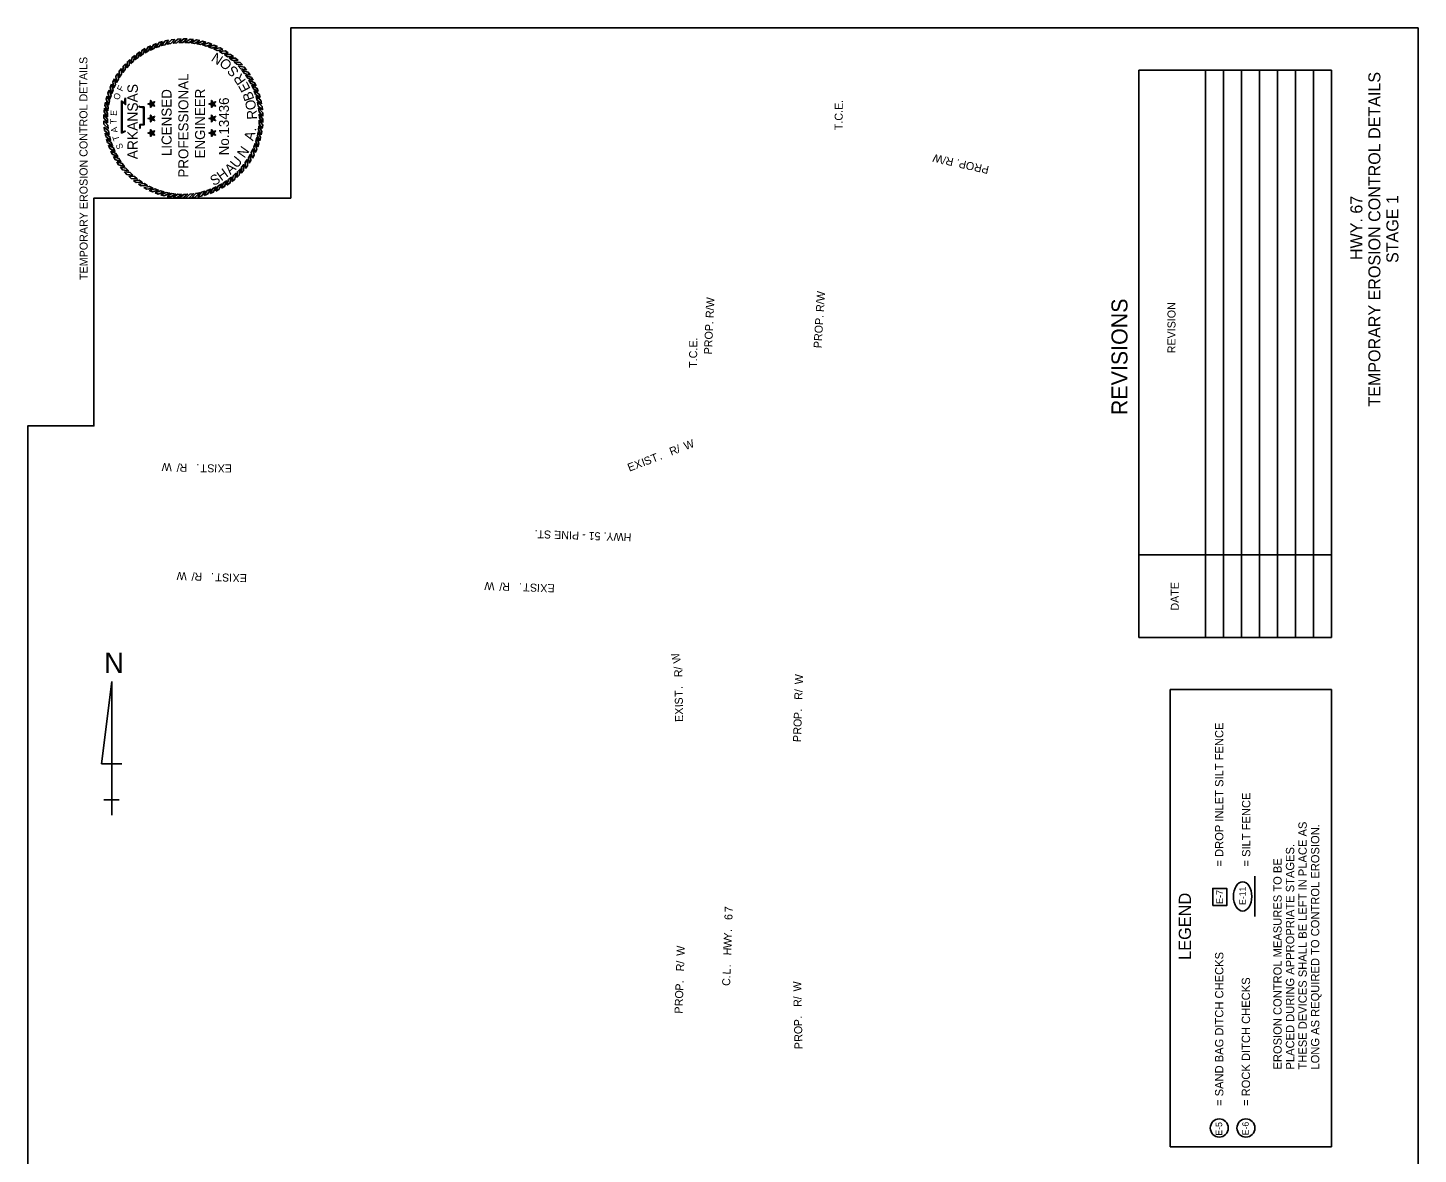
# Model space of a CAD drawing. Extents: x 991974 to 993016, y 1842702 to 1844298.
# Drawn here: x 991974 to 993016, y 1843454 to 1844298 of the extents above; entities that cross this region are included whole.
import ezdxf

# ---------------------------------------------------------------- set-up
doc = ezdxf.new("R2010")
doc.units = 0
for name, color, linetype in [('1', 7, 'Continuous'), ('60', 7, 'Continuous'), ('63', 7, 'Continuous'), ('Default', 7, 'Continuous'), ('G-ANNO-SYMB', 7, 'Continuous'), ('G-ANNO-TEXT', 7, 'Continuous'), ('G-Border-Sheet', 7, 'Continuous'), ('Level 1', 7, 'Continuous'), ('Level 44', 7, 'Continuous'), ('R_Draft', 7, 'Continuous')]:
    doc.layers.add(name, color=color, linetype=linetype)

msp = doc.modelspace()

# ---------------------------------------------------------------- linework, layer by layer
at = {"layer": '1'}
msp.add_lwpolyline([(992862.3, 1843640.1), (992862.3, 1843652.9), (992872.8, 1843652.9), (992872.8, 1843640.1)], close=True, dxfattribs=at)
at = {"layer": '63'}
for p, q in [((992036.9, 1843807.9), (992029.2, 1843746.4)), ((992036.9, 1843707.9), (992036.9, 1843807.9)), ((992036.9, 1843807.9), (992036.9, 1843731)), ((992029.2, 1843746.4), (992044.6, 1843746.4)), ((992036.9, 1843707.9), (992036.9, 1843731)), ((992036.9, 1843719.4), (992031.1, 1843719.4)), ((992031.1, 1843719.4), (992042.6, 1843719.4)), ((992036.9, 1843707.9), (992036.9, 1843719.4))]:
    msp.add_line(p, q, dxfattribs=at)
at = {"layer": 'Default'}
msp.add_lwpolyline([(993016.3, 1842702.5), (991974, 1842702.5), (991974, 1843999.5), (992023.6, 1843999.5), (992023.6, 1844170.3), (992171.1, 1844170.3), (992171.1, 1844297.8), (993016.3, 1844297.8)], close=True, dxfattribs=at)
at = {"layer": 'G-ANNO-SYMB'}
for points in [[(992062, 1844282.3), (992059.8, 1844281), (992058.2, 1844276.7), (992060.5, 1844278.3)], [(992066.2, 1844284.4), (992063.9, 1844283.3), (992062, 1844279.1), (992064.4, 1844280.5)], [(992070.6, 1844286.1), (992068.2, 1844285.2), (992065.9, 1844281.2), (992068.5, 1844282.4)], [(992075, 1844287.5), (992072.6, 1844286.8), (992070, 1844283), (992072.6, 1844283.9)], [(992079.6, 1844288.6), (992077.1, 1844288), (992074.3, 1844284.5), (992076.9, 1844285.2)], [(992084.2, 1844289.2), (992081.7, 1844288.9), (992078.6, 1844285.6), (992081.3, 1844286.1)], [(992088.9, 1844289.6), (992086.4, 1844289.4), (992083, 1844286.3), (992085.7, 1844286.7)], [(992093.6, 1844289.5), (992091, 1844289.6), (992087.4, 1844286.8), (992090.2, 1844286.9)], [(992098.3, 1844289.1), (992095.7, 1844289.4), (992091.9, 1844286.8), (992094.7, 1844286.7)], [(992102.9, 1844288.3), (992100.4, 1844288.8), (992096.4, 1844286.6), (992099.1, 1844286.2)], [(992107.4, 1844287.2), (992105, 1844287.8), (992100.8, 1844285.9), (992103.5, 1844285.4)], [(992111.9, 1844285.7), (992109.5, 1844286.5), (992105.2, 1844285), (992107.8, 1844284.2)], [(992116.2, 1844283.8), (992113.8, 1844284.9), (992109.4, 1844283.7), (992112, 1844282.7)], [(992120.3, 1844281.7), (992118.1, 1844282.9), (992113.6, 1844282), (992116.1, 1844280.8)], [(992047.3, 1844270.9), (992045.5, 1844269), (992045.3, 1844264.4), (992047.1, 1844266.6)], [(992050.6, 1844274.2), (992048.7, 1844272.4), (992048.2, 1844267.9), (992050.1, 1844269.9)], [(992054.2, 1844277.2), (992052.2, 1844275.6), (992051.3, 1844271.1), (992053.3, 1844272.9)], [(992058, 1844279.9), (992055.9, 1844278.4), (992054.6, 1844274), (992056.8, 1844275.7)], [(992124.3, 1844279.2), (992122.2, 1844280.6), (992117.6, 1844280.1), (992120, 1844278.7)], [(992128.1, 1844276.4), (992126, 1844277.9), (992121.5, 1844277.8), (992123.8, 1844276.2)], [(992131.6, 1844273.3), (992129.7, 1844275), (992125.1, 1844275.2), (992127.3, 1844273.5)], [(992134.9, 1844270), (992133.1, 1844271.8), (992128.6, 1844272.4), (992130.6, 1844270.5)], [(992041.4, 1844263.6), (992040, 1844261.5), (992040.5, 1844256.9), (992041.9, 1844259.3)], [(992044.2, 1844267.4), (992042.6, 1844265.3), (992042.8, 1844260.8), (992044.3, 1844263.1)], [(992137.9, 1844266.4), (992136.3, 1844268.4), (992131.8, 1844269.3), (992133.6, 1844267.2)], [(992140.6, 1844262.5), (992139.1, 1844264.7), (992134.7, 1844265.9), (992136.4, 1844263.7)], [(992143, 1844258.5), (992141.7, 1844260.7), (992137.4, 1844262.3), (992139, 1844260)], [(992034.9, 1844251.2), (992034, 1844248.8), (992035.6, 1844244.5), (992036.4, 1844247.1)], [(992036.7, 1844255.5), (992035.7, 1844253.1), (992036.9, 1844248.7), (992037.9, 1844251.3)], [(992038.9, 1844259.6), (992037.7, 1844257.4), (992038.5, 1844252.9), (992039.7, 1844255.4)], [(992145.1, 1844254.3), (992144, 1844256.6), (992139.8, 1844258.6), (992141.2, 1844256.1)], [(992146.8, 1844250), (992145.9, 1844252.4), (992141.9, 1844254.6), (992143.1, 1844252.1)], [(992148.2, 1844245.5), (992147.5, 1844248), (992143.7, 1844250.5), (992144.6, 1844247.9)], [(992032.2, 1844242.2), (992031.8, 1844239.7), (992034, 1844235.7), (992034.3, 1844238.4)], [(992033.4, 1844246.7), (992032.7, 1844244.3), (992034.6, 1844240.1), (992035.2, 1844242.8)], [(992066.9, 1844240.8), (992066, 1844241.4), (992064.1, 1844240.8), (992066, 1844240.2)], [(992066.9, 1844240.8), (992067.2, 1844241.8), (992066, 1844243.4), (992066, 1844241.4)], [(992066.9, 1844240.8), (992066, 1844240.2), (992066, 1844238.2), (992067.2, 1844239.8)], [(992066.9, 1844240.8), (992067.9, 1844240.8), (992069.1, 1844242.4), (992067.2, 1844241.8)], [(992066.9, 1844240.8), (992067.2, 1844239.8), (992069.1, 1844239.2), (992067.9, 1844240.8)], [(992112.6, 1844240.8), (992111.7, 1844241.4), (992109.8, 1844240.8), (992111.7, 1844240.2)], [(992112.6, 1844240.8), (992112.9, 1844241.8), (992111.7, 1844243.4), (992111.7, 1844241.4)], [(992112.6, 1844240.8), (992111.7, 1844240.2), (992111.7, 1844238.2), (992112.9, 1844239.8)], [(992112.6, 1844240.8), (992113.6, 1844240.8), (992114.8, 1844242.4), (992112.9, 1844241.8)], [(992112.6, 1844240.8), (992112.9, 1844239.8), (992114.8, 1844239.2), (992113.6, 1844240.8)], [(992149.3, 1844240.9), (992148.7, 1844243.5), (992145.2, 1844246.3), (992145.9, 1844243.6)], [(992149.9, 1844236.3), (992149.6, 1844238.9), (992146.3, 1844242), (992146.8, 1844239.2)], [(992031, 1844232.9), (992031, 1844230.3), (992033.8, 1844226.7), (992033.7, 1844229.5)], [(992031.5, 1844237.6), (992031.2, 1844235), (992033.7, 1844231.2), (992033.8, 1844234)], [(992066.9, 1844229.9), (992066, 1844230.5), (992064.1, 1844229.9), (992066, 1844229.3)], [(992066.9, 1844229.9), (992067.2, 1844230.9), (992066, 1844232.5), (992066, 1844230.5)], [(992066.9, 1844229.9), (992066, 1844229.3), (992066, 1844227.3), (992067.2, 1844228.9)], [(992066.9, 1844229.9), (992067.9, 1844229.9), (992069.1, 1844231.5), (992067.2, 1844230.9)], [(992066.9, 1844229.9), (992067.2, 1844228.9), (992069.1, 1844228.3), (992067.9, 1844229.9)], [(992112.6, 1844229.9), (992111.7, 1844230.5), (992109.8, 1844229.9), (992111.7, 1844229.3)], [(992112.6, 1844229.9), (992112.9, 1844230.9), (992111.7, 1844232.5), (992111.7, 1844230.5)], [(992112.6, 1844229.9), (992111.7, 1844229.3), (992111.7, 1844227.3), (992112.9, 1844228.9)], [(992112.6, 1844229.9), (992113.6, 1844229.9), (992114.8, 1844231.5), (992112.9, 1844230.9)], [(992112.6, 1844229.9), (992112.9, 1844228.9), (992114.8, 1844228.3), (992113.6, 1844229.9)], [(992150.3, 1844231.6), (992150.1, 1844234.2), (992147, 1844237.6), (992147.4, 1844234.8)], [(992150.2, 1844226.9), (992150.3, 1844229.5), (992147.5, 1844233.1), (992147.6, 1844230.3)], [(992031, 1844228.2), (992031.1, 1844225.7), (992034.2, 1844222.3), (992033.9, 1844225)], [(992031.3, 1844223.5), (992031.6, 1844221), (992035, 1844217.9), (992034.5, 1844220.6)], [(992032, 1844218.9), (992032.5, 1844216.4), (992036.1, 1844213.6), (992035.4, 1844216.2)], [(992066.9, 1844219), (992066, 1844219.6), (992064.1, 1844219), (992066, 1844218.4)], [(992066.9, 1844219), (992067.2, 1844220), (992066, 1844221.6), (992066, 1844219.6)], [(992066.9, 1844219), (992066, 1844218.4), (992066, 1844216.4), (992067.2, 1844218)], [(992066.9, 1844219), (992067.9, 1844219), (992069.1, 1844220.6), (992067.2, 1844220)], [(992066.9, 1844219), (992067.2, 1844218), (992069.1, 1844217.4), (992067.9, 1844219)], [(992112.6, 1844219), (992111.7, 1844219.6), (992109.8, 1844219), (992111.7, 1844218.4)], [(992112.6, 1844219), (992112.9, 1844220), (992111.7, 1844221.6), (992111.7, 1844219.6)], [(992112.6, 1844219), (992111.7, 1844218.4), (992111.7, 1844216.4), (992112.9, 1844218)], [(992112.6, 1844219), (992113.6, 1844219), (992114.8, 1844220.6), (992112.9, 1844220)], [(992112.6, 1844219), (992112.9, 1844218), (992114.8, 1844217.4), (992113.6, 1844219)], [(992147.9, 1844213.1), (992148.5, 1844215.6), (992146.6, 1844219.8), (992146.1, 1844217)], [(992149, 1844217.7), (992149.5, 1844220.2), (992147.3, 1844224.2), (992146.9, 1844221.4)], [(992149.8, 1844222.3), (992150.1, 1844224.8), (992147.5, 1844228.6), (992147.4, 1844225.9)], [(992033, 1844214.3), (992033.8, 1844211.9), (992037.6, 1844209.3), (992036.6, 1844211.9)], [(992034.4, 1844209.9), (992035.4, 1844207.5), (992039.3, 1844205.2), (992038.2, 1844207.8)], [(992144.5, 1844204.4), (992145.6, 1844206.7), (992144.4, 1844211.1), (992143.4, 1844208.5)], [(992146.4, 1844208.7), (992147.2, 1844211.1), (992145.7, 1844215.4), (992144.9, 1844212.7)], [(992036.2, 1844205.5), (992037.3, 1844203.2), (992041.4, 1844201.3), (992040.1, 1844203.7)], [(992038.3, 1844201.3), (992039.5, 1844199.1), (992043.8, 1844197.5), (992042.3, 1844199.8)], [(992137.1, 1844192.5), (992138.6, 1844194.5), (992138.5, 1844199.1), (992136.9, 1844196.8)], [(992139.9, 1844196.3), (992141.3, 1844198.4), (992140.8, 1844202.9), (992139.4, 1844200.5)], [(992142.4, 1844200.2), (992143.6, 1844202.5), (992142.7, 1844207), (992141.5, 1844204.5)], [(992040.7, 1844197.3), (992042.1, 1844195.2), (992046.5, 1844193.9), (992044.8, 1844196.1)], [(992043.4, 1844193.5), (992045, 1844191.5), (992049.5, 1844190.6), (992047.6, 1844192.6)], [(992046.4, 1844189.9), (992048.2, 1844188), (992052.7, 1844187.5), (992050.7, 1844189.4)], [(992127.1, 1844182.7), (992129.1, 1844184.3), (992130, 1844188.8), (992127.9, 1844186.9)], [(992130.7, 1844185.7), (992132.5, 1844187.5), (992133.1, 1844192), (992131.2, 1844190)], [(992134, 1844189), (992135.7, 1844190.9), (992135.9, 1844195.4), (992134.2, 1844193.3)], [(992049.7, 1844186.6), (992051.6, 1844184.8), (992056.1, 1844184.6), (992054, 1844186.4)], [(992053.2, 1844183.5), (992055.2, 1844181.9), (992059.8, 1844182.1), (992057.5, 1844183.6)], [(992057, 1844180.7), (992059.1, 1844179.3), (992063.6, 1844179.8), (992061.2, 1844181.2)], [(992060.9, 1844178.2), (992063.2, 1844177), (992067.7, 1844177.8), (992065.2, 1844179)], [(992065.1, 1844176), (992067.4, 1844175), (992071.8, 1844176.2), (992069.2, 1844177.2)], [(992106.2, 1844172.3), (992108.7, 1844173.1), (992111.2, 1844176.9), (992108.6, 1844175.9)], [(992110.7, 1844173.7), (992113.1, 1844174.7), (992115.3, 1844178.6), (992112.8, 1844177.5)], [(992115, 1844175.5), (992117.3, 1844176.6), (992119.3, 1844180.7), (992116.8, 1844179.4)], [(992119.2, 1844177.6), (992121.4, 1844178.8), (992123, 1844183.1), (992120.7, 1844181.6)], [(992123.2, 1844180), (992125.4, 1844181.4), (992126.6, 1844185.8), (992124.4, 1844184.1)], [(992069.4, 1844174.2), (992071.8, 1844173.3), (992076.1, 1844174.9), (992073.4, 1844175.7)], [(992073.8, 1844172.7), (992076.3, 1844172), (992080.5, 1844173.9), (992077.7, 1844174.5)], [(992078.4, 1844171.5), (992080.9, 1844171.1), (992084.9, 1844173.3), (992082.1, 1844173.6)], [(992083, 1844170.8), (992085.5, 1844170.5), (992089.3, 1844173), (992086.6, 1844173.1)], [(992087.6, 1844170.3), (992090.2, 1844170.3), (992093.8, 1844173.1), (992091, 1844173)], [(992092.3, 1844170.3), (992094.9, 1844170.4), (992098.3, 1844173.5), (992095.5, 1844173.2)], [(992097, 1844170.6), (992099.6, 1844170.9), (992102.7, 1844174.3), (992099.9, 1844173.8)], [(992101.6, 1844171.3), (992104.2, 1844171.8), (992107, 1844175.4), (992104.3, 1844174.7)]]:
    msp.add_lwpolyline(points, close=True, dxfattribs=at)
for points in [[(992047.3, 1844220.4), (992044.3, 1844219), (992044.3, 1844243), (992046.8, 1844241), (992046.8, 1844242.7), (992046.8, 1844244), (992046.9, 1844245.4)], [(992047.2, 1844220.7), (992044.7, 1844219.6), (992044.7, 1844242.3), (992047.2, 1844240.2), (992047.2, 1844242.7), (992047.2, 1844244), (992047.3, 1844245.4)], [(992057.1, 1844239), (992057.5, 1844238.5), (992058.2, 1844238.3), (992059.5, 1844238.2), (992060.8, 1844238.2), (992060.8, 1844225.5), (992058.9, 1844225.5), (992058.1, 1844225.5), (992057.9, 1844224.6), (992057.9, 1844222.9), (992057.5, 1844222.7)], [(992057.4, 1844239.3), (992057.7, 1844238.8), (992058.2, 1844238.7), (992059.5, 1844238.6), (992061.2, 1844238.6), (992061.2, 1844225.1), (992058.9, 1844225.1), (992058.4, 1844225.1), (992058.2, 1844224.6), (992058.2, 1844222.7), (992057.7, 1844222.3)]]:
    msp.add_lwpolyline(points, dxfattribs=at)
at = {"layer": 'G-Border-Sheet'}
for p, q in [((992951.4, 1843801.9), (992830.3, 1843801.9)), ((992830.3, 1843459.3), (992830.3, 1843801.9)), ((992951.4, 1843459.3), (992951.4, 1843801.9)), ((992951.4, 1843459.3), (992830.3, 1843459.3))]:
    msp.add_line(p, q, dxfattribs=at)
at = {"layer": 'Level 1'}
for centre, major_axis, ratio in [((992884.7, 1843646.9), (0, 11), 0.622952), ((992867.2, 1843473.4), (0, -6.88), 0.97521), ((992887.2, 1843473.4), (0, -6.88), 0.97521)]:
    msp.add_ellipse(centre, major_axis=major_axis, ratio=ratio, dxfattribs=at)
at = {"layer": 'Level 44'}
msp.add_lwpolyline([(992894, 1843631.8), (992894, 1843662)], dxfattribs=at)
at = {"layer": 'R_Draft'}
for p, q in [((992806.9, 1843841), (992806.9, 1844266)), ((992806.9, 1844266), (992951.4, 1844266)), ((992856.9, 1843841), (992856.9, 1844266)), ((992870.4, 1843841), (992870.4, 1844266)), ((992883.9, 1843841), (992883.9, 1844266)), ((992897.4, 1843841), (992897.4, 1844266)), ((992897.4, 1843841), (992897.4, 1844266)), ((992910.9, 1843841), (992910.9, 1844266)), ((992924.4, 1843841), (992924.4, 1844266)), ((992937.9, 1843841), (992937.9, 1844266)), ((992951.4, 1843841), (992951.4, 1844266)), ((992806.9, 1843902.8), (992951.4, 1843902.8)), ((992806.9, 1843841), (992951.4, 1843841))]:
    msp.add_line(p, q, dxfattribs=at)

# ---------------------------------------------------------------- texts
at = {"layer": '1'}
msp.add_text('E-7 ', height=5, rotation=89.6121, dxfattribs=at).set_placement((992870, 1843641.3))
at = {"layer": '60'}
for s, p in [('TEMPORARY EROSION CONTROL DETAILS', (992988, 1844014)), ('HWY. 67 ', (992974.5, 1844123.8)), (' STAGE 1 ', (993001.5, 1844118.3))]:
    msp.add_text(s, height=9, rotation=90, dxfattribs=at).set_placement(p)
at = {"layer": '63'}
msp.add_text('N', height=15.4, rotation=0, dxfattribs=at).set_placement((992031.2, 1843814.3))
at = {"layer": 'G-ANNO-SYMB'}
for s, height, rotation, p in [('N', 7.5, 146.1007, (992121.1, 1844275.7)), ('O', 7.5, 134.7757, (992127.8, 1844270.5)), ('PROFESSIONAL', 7.5, 90, (992094.4, 1844185.6)), ('S', 7.5, 133.4878, (992132.8, 1844265.3)), ('R', 7.5, 125.6597, (992137.9, 1844258.4)), ('F', 4.75, 65.3628, (992044.9, 1844249.8)), ('ARKANSAS', 7.75, 90, (992056.5, 1844199.3)), ('LICENSED', 7.5, 90, (992081.8, 1844201.7)), ('ENGINEER', 7.5, 90, (992106.9, 1844199.9)), ('E', 7.5, 117.8315, (992141.2, 1844252.1)), ('B', 7.5, 108.885, (992143.9, 1844244.5)), ('O', 4.75, 71.2218, (992042.4, 1844243.4)), ('No.13436', 7.47, 90, (992124.8, 1844202.3)), ('O', 7.5, 101.4296, (992145.5, 1844237)), ('T', 4.75, 91.4789, (992040.6, 1844225.8)), ('E', 4.75, 86.672, (992040.7, 1844231.8)), ('R', 7.5, 93.2287, (992146, 1844229.3)), ('A', 4.75, 98.6788, (992041.5, 1844219.6)), ('A', 7.5, 73.0991, (992142.9, 1844212.7)), ('.', 7.5, 81.3, (992145, 1844220.1)), ('T', 4.75, 106.9015, (992043, 1844213.9)), ('S', 4.75, 109.7726, (992045.7, 1844207.8)), ('N', 7.5, 54.9326, (992136.4, 1844199.7)), ('U', 7.5, 50.9026, (992130.8, 1844192.1)), ('S', 7.5, 28.1636, (992113.2, 1844179.2)), ('H', 7.5, 35.619, (992119.1, 1844182.7)), ('A', 7.5, 43.4472, (992125.9, 1844187.4))]:
    msp.add_text(s, height=height, rotation=rotation, dxfattribs=at).set_placement(p)
at = {"layer": 'G-ANNO-TEXT'}
msp.add_text('TEMPORARY EROSION CONTROL DETAILS', height=6, rotation=90.0791, dxfattribs=at).set_placement((992018.9, 1844108.9))
at = {"layer": 'Level 1'}
for s, height, p in [('= DROP INLET SILT FENCE', 6.25, (992870.3, 1843669.3)), ('= SILT FENCE', 6.25, (992890.5, 1843669.3)), ('THESE DEVICES SHALL BE LEFT IN PLACE AS ', 6.25, (992932.8, 1843517.2)), ('LONG AS REQUIRED TO CONTROL EROSION.', 6.25, (992942.2, 1843517.2)), ('PLACED DURING APPROPRIATE STAGES. ', 6.25, (992923.4, 1843517.2)), ('EROSION CONTROL MEASURES TO BE', 6.25, (992914, 1843517.2)), ('E-11 ', 4.88, (992887.1, 1843640.5)), ('= SAND BAG DITCH CHECKS', 6.25, (992870.3, 1843489.9)), ('= ROCK DITCH CHECKS', 6.25, (992890.3, 1843489.9)), ('E-5 ', 4.88, (992869.4, 1843467.7)), ('E-6 ', 4.88, (992889.3, 1843467.9))]:
    msp.add_text(s, height=height, rotation=90, dxfattribs=at).set_placement(p)
at = {"layer": 'Level 44'}
msp.add_text('LEGEND', height=9.14, rotation=90, dxfattribs=at).set_placement((992846, 1843599.4))
at = {"layer": 'R_Draft'}
for s, height, rotation, p in [('T.C.E.', 6, 89.409, (992584.8, 1844221.1)), ('PROP. R/W', 6, 167.4482, (992695, 1844194.1)), ('PROP. R/W', 6, 87.2827, (992486.8, 1844053)), ('PROP. R/W', 6, 86.3656, (992569, 1844057.6)), ('REVISIONS', 12, 90, (992798.4, 1844007.6)), ('REVISION', 6, 90, (992834.4, 1844053.9)), ('T.C.E.', 6, 89.409, (992475.7, 1844043)), ('W', 6, 20.9463, (992467.2, 1843981.3)), ('T', 6, 20.9463, (992442.6, 1843971.9)), ('R', 6, 20.9463, (992456.4, 1843977.2)), ('/', 6, 20.9463, (992461.7, 1843979.2)), ('W', 6, 178.2446, (992082.1, 1843971.5)), ('/', 6, 178.2446, (992088, 1843971.3)), ('R', 6, 178.2446, (992093.6, 1843971.1)), ('.', 6, 178.2446, (992102.6, 1843970.9)), ('T', 6, 179.3022, (992108.3, 1843970.8)), ('S', 6, 179.3022, (992114, 1843970.7)), ('I', 6, 179.3022, (992116, 1843970.7)), ('X', 6, 179.3022, (992121.7, 1843970.6)), ('E', 6, 179.3022, (992127.1, 1843970.6)), ('E', 6, 20.9463, (992425, 1843965.2)), ('X', 6, 20.9463, (992430.1, 1843967.1)), ('I', 6, 20.9463, (992435.5, 1843969.1)), ('S', 6, 20.9463, (992437.3, 1843969.8)), ('.', 6, 20.9463, (992448.1, 1843974)), ('HWY. 51 - PINE ST.', 6, 178.0557, (992426.6, 1843919)), ('W', 6, 178.1599, (992093.3, 1843889.8)), ('/', 6, 178.1599, (992099.1, 1843889.6)), ('R', 6, 178.1599, (992104.8, 1843889.5)), ('.', 6, 178.1599, (992113.7, 1843889.2)), ('T', 6, 178.1599, (992119.6, 1843889)), ('S', 6, 178.1599, (992125.2, 1843888.8)), ('I', 6, 178.1599, (992127.2, 1843888.7)), ('X', 6, 178.1599, (992133, 1843888.6)), ('E', 6, 178.1599, (992138.4, 1843888.4)), ('W', 6, 178.0557, (992324, 1843882.3)), ('/', 6, 178.0557, (992329.9, 1843882.1)), ('R', 6, 178.0557, (992335.5, 1843881.9)), ('.', 6, 178.0557, (992344.4, 1843881.6)), ('T', 6, 178.0557, (992350.3, 1843881.4)), ('S', 6, 178.0557, (992356, 1843881.2)), ('I', 6, 178.0557, (992358, 1843881.1)), ('X', 6, 178.0557, (992363.7, 1843880.9)), ('E', 6, 178.0557, (992369.1, 1843880.8)), ('DATE', 6, 90, (992836.9, 1843861.1)), ('W', 6, 104.9141, (992463.8, 1843822.7)), ('/', 6, 91.0262, (992464.6, 1843816.9)), ('R', 6, 91.0262, (992464.7, 1843811.3)), ('W', 6, 88.2004, (992555, 1843805.8)), ('.', 6, 91.0262, (992464.9, 1843802.3)), ('/', 6, 88.2004, (992554.8, 1843799.9)), ('T', 6, 91.0262, (992465, 1843796.5)), ('S', 6, 91.0262, (992465.1, 1843790.8)), ('R', 6, 88.2004, (992554.6, 1843794.2)), ('I', 6, 91.0262, (992465.1, 1843788.8)), ('X', 6, 91.0262, (992465.2, 1843783.1)), ('E', 6, 91.0262, (992465.3, 1843777.7)), ('P', 6, 88.2004, (992554.2, 1843779.7)), ('.', 6, 88.2004, (992554.3, 1843785.3)), ('R', 6, 88.2004, (992553.8, 1843768.1)), ('O', 6, 88.2004, (992554, 1843773.8)), ('P', 6, 88.2004, (992553.6, 1843762.5)), ('7', 6, 88.0361, (992502.4, 1843634.9)), ('6', 6, 88.0361, (992502.2, 1843629.2)), ('W', 6, 88.0361, (992501.5, 1843608.1)), ('Y', 6, 88.0361, (992501.7, 1843614.5)), ('.', 6, 88.0361, (992501.9, 1843620.3)), ('W', 6, 88.0361, (992466.3, 1843602.3)), ('H', 6, 88.0361, (992501.3, 1843602.7)), ('/', 6, 88.0361, (992466.1, 1843596.4)), ('R', 6, 88.0361, (992465.9, 1843590.7)), ('.', 6, 88.0361, (992501, 1843593.8)), ('.', 6, 88.0361, (992465.6, 1843581.8)), ('C', 6, 88.0361, (992500.5, 1843579.8)), ('L', 6, 88.0361, (992500.8, 1843588.4)), ('.', 6, 88.0361, (992500.7, 1843585.5)), ('W', 6, 91.2159, (992553.9, 1843575.8)), ('O', 6, 88.0361, (992465.2, 1843570.3)), ('P', 6, 88.0361, (992465.4, 1843576.2)), ('P', 6, 88.0361, (992464.8, 1843559)), ('R', 6, 88.0361, (992465, 1843564.6)), ('/', 6, 91.2159, (992554, 1843569.9)), ('R', 6, 91.2159, (992554.1, 1843564.2)), ('P', 6, 91.2159, (992554.5, 1843549.7)), ('.', 6, 91.2159, (992554.3, 1843555.3)), ('O', 6, 91.2159, (992554.6, 1843543.8)), ('R', 6, 91.2159, (992554.7, 1843538.1)), ('P', 6, 91.2159, (992554.8, 1843532.5))]:
    msp.add_text(s, height=height, rotation=rotation, dxfattribs=at).set_placement(p)

doc.saveas('drawing.dxf')
